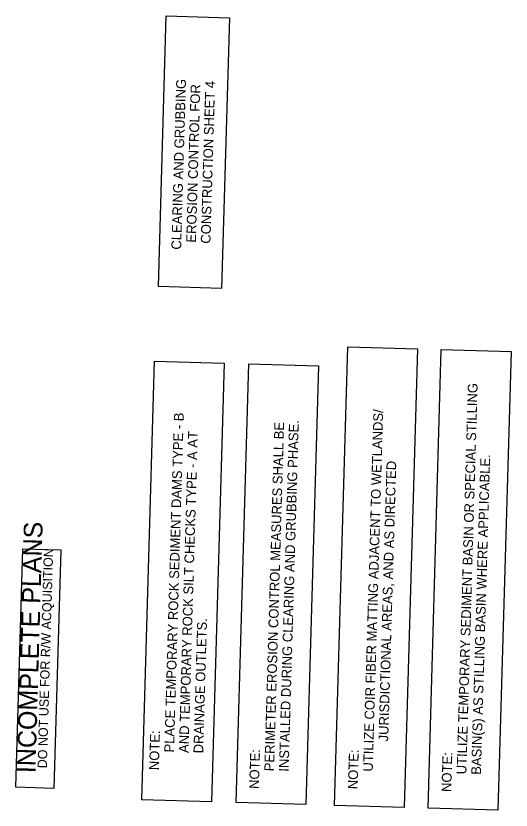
# Model space of a CAD drawing. Extents: x 2096976 to 2098492, y 681809 to 689636.
# Drawn here: x 2097701.9 to 2098007.3, y 681809.1 to 682298.5 of the extents above; entities that cross this region are included whole.
import ezdxf

# ---------------------------------------------------------------- set-up
doc = ezdxf.new("R2010")
doc.units = 0
for name, color, linetype in [('Construction Sheet Number Note CG CELL', 7, 'Continuous'), ('Sediment Dams and Silt Check Note CG CELL', 7, 'Continuous'), ('Sheet Layout Plan Border', 7, 'Continuous')]:
    doc.layers.add(name, color=color, linetype=linetype)

# ---------------------------------------------------------------- blocks, each defined once
blk = doc.blocks.new('CGNT2')
at = {"layer": 'Sediment Dams and Silt Check Note CG CELL'}
blk.add_lwpolyline([(-2.704, 0.431), (2.704, 0.43125), (2.704, -0.43), (-2.704, -0.43)], close=True, dxfattribs=at)
for s, p in [('NOTE:', (-2.335, 0.231)), ('     PLACE TEMPORARY ROCK SEDIMENT DAMS TYPE - B', (-2.335, 0.05125)), ('     AND TEMPORARY ROCK SILT CHECKS TYPE - A AT', (-2.335, -0.129)), ('     DRAINAGE OUTLETS.', (-2.335, -0.309))]:
    blk.add_text(s, height=0.12, dxfattribs=at).set_placement(p)

msp = doc.modelspace()

# ---------------------------------------------------------------- linework, layer by layer
at = {"layer": 'Construction Sheet Number Note CG CELL'}
for points in [[(2097898.34, 681812.02), (2097906.55, 682094.59), (2097949.58, 682093.34), (2097941.37, 681810.77)], [(2097956.04, 681810.34), (2097964.25, 682092.91), (2098007.28, 682091.66), (2097999.07, 681809.09)]]:
    msp.add_lwpolyline(points, close=True, dxfattribs=at)
at = {"layer": 'Sediment Dams and Silt Check Note CG CELL'}
for points in [[(2097789.81, 682131.63), (2097794.67, 682298.45), (2097833.66, 682297.32), (2097828.81, 682130.49)], [(2097837.72, 681813.78), (2097845.58, 682084.06), (2097888.61, 682082.81), (2097880.76, 681812.53)]]:
    msp.add_lwpolyline(points, close=True, dxfattribs=at)
at = {"layer": 'Sheet Layout Plan Border'}
msp.add_lwpolyline([(2097725.44, 681822.46), (2097701.95, 681823.14), (2097706.22, 681970.08), (2097729.71, 681969.39)], close=True, dxfattribs=at)

# ---------------------------------------------------------------- block references
at = {"layer": 'Sediment Dams and Silt Check Note CG CELL', "xscale": 50.00000000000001, "yscale": 49.99999999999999, "rotation": 88.33482999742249}
msp.add_blockref('CGNT2', (2097805.02, 681949.99), dxfattribs=at)

# ---------------------------------------------------------------- texts
at = {"layer": 'Construction Sheet Number Note CG CELL'}
for s, p in [('     UTILIZE TEMPORARY SEDIMENT BASIN OR SPECIAL STILLING', (2097979.32, 681819.92)), ('     UTILIZE COIR FIBER MATTING ADJACENT TO WETLANDS/', (2097921.62, 681821.6)), ('     BASIN(S) AS STILLING BASIN WHERE APPLICABLE.', (2097988.32, 681819.67)), ('JURISDICTIONAL AREAS, AND AS DIRECTED', (2097931.49, 681851.33)), ('NOTE:  ', (2097912.63, 681821.87)), ('NOTE:  ', (2097970.33, 681820.19))]:
    msp.add_text(s, height=6, rotation=88.3348, dxfattribs=at).set_placement(p)
at = {"layer": 'Sediment Dams and Silt Check Note CG CELL'}
for s, p in [('CLEARING AND GRUBBING', (2097803.79, 682154.36)), ('EROSION CONTROL FOR', (2097812.92, 682158.69)), ('CONSTRUCTION SHEET 4', (2097821.9, 682158.03)), ('     PERIMETER EROSION CONTROL MEASURES SHALL BE', (2097860.76, 681821.81)), ('     INSTALLED DURING CLEARING AND GRUBBING PHASE.', (2097869.76, 681821.55)), ('NOTE:', (2097851.77, 681822.07))]:
    msp.add_text(s, height=6, rotation=88.3348, dxfattribs=at).set_placement(p)
at = {"layer": 'Sheet Layout Plan Border'}
for s, height, p in [('INCOMPLETE PLANS', 11.52, (2097714, 681831.74)), ('DO NOT USE FOR R/W ACQUISITION', 5.76, (2097721.04, 681834.79))]:
    msp.add_text(s, height=height, rotation=88.3348, dxfattribs=at).set_placement(p)

doc.saveas('drawing.dxf')
